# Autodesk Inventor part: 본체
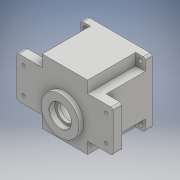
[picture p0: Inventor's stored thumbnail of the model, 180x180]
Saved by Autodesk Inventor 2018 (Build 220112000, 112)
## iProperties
Created: 2020-07
Part Number: 본체
Material: 일반
Document SubType Name: Modeling
Designer: Admin
Density: 1 g/cm^3
Appearance: 기본값
Author: Admin
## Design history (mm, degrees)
sketch "스케치1"
  geometry: L1 (0, -65.8)-(0, 65.8) reference; L2 (-98, 0)-(98, 0) reference; L3 (33, 47)-(-33, 47); L4 (-33, 47)-(-33, 30); L5 (-33, 30)-(-70, 30); L6 (-70, 30)-(-70, -30); L7 (-70, -30)-(-33, -30); L8 (-33, -30)-(-33, -47); L9 (-33, -47)-(33, -47); L10 (33, -47)-(33, -30); L11 (33, -30)-(70, -30); L12 (70, -30)-(70, 30); L13 (70, 30)-(33, 30); L14 (33, 47)-(33, 30); 1 further point
  constraints: 24 end point, 8 perpendicular, 7 point on line, 1 horizontal, 3 other
  dimensions: "d0" = 140 distance between parallel lines of L6 L12; "d1" = 60 distance between parallel lines of L7 L5; "d2" = 66 distance of L3.start L3.end; "d3" = 17 distance of L3.end L4.end; "d4" = 17 distance of L7.end L8.end
extrude "돌출1" new body sketch "스케치1" distance "d5" = 13; taper "d6" = 0 deg
sketch "스케치2"
  geometry: L1 (-33, -47)-(33, -47) reference; L2 (33, -47)-(33, -30) reference; L3 (33, -30)-(70, -30) reference; L4 (70, -30)-(70, 30) reference; L5 (70, 30)-(33, 30) reference; L6 (33, 30)-(33, 47) reference; L7 (33, 47)-(-33, 47) reference; L8 (-33, 47)-(-33, 30) reference; L9 (-33, 30)-(-70, 30) reference; L10 (-70, 30)-(-70, -30) reference; L11 (-70, -30)-(-33, -30) reference; L12 (-33, -30)-(-33, -47) reference; L13 (-47, -47)-(47, -47); L14 (47, -47)-(47, 47); L15 (47, 47)-(-47, 47); L16 (-47, 47)-(-47, -47); L17 (-47, -47)-(47, 47); L18 (47, -47)-(-47, 47); 1 further point
  constraints: 12 end point, 2 midpoint, 2 parallel, 1 horizontal, 1 perpendicular
  dimensions: "d7" = 94 distance of L14.end L15.end; "d8" = 94 distance of L13.end L14.end
extrude "돌출2" join sketch "스케치2" distance "d9" = 67; taper "d10" = 0 deg
sketch "스케치3"
  geometry: L1 (-33, 47)-(33, 47) reference; L2 (-33, 30)-(-33, 47) reference; L3 (-70, 30)-(-33, 30) reference; L4 (-70, -30)-(-70, 30) reference; L5 (-33, -30)-(-70, -30) reference; L6 (-33, -47)-(-33, -30) reference; L7 (33, -47)-(-33, -47) reference; L8 (33, -30)-(33, -47) reference; L9 (70, -30)-(33, -30) reference; L10 (70, 30)-(70, -30) reference; L11 (33, 30)-(70, 30) reference; L12 (33, 47)-(33, 30) reference; L13 (33, 47)-(47, 47) reference; L14 (47, 47)-(47, 30) reference; L15 (47, -30)-(47, -47) reference; L16 (47, -47)-(33, -47) reference; L17 (-33, -47)-(-47, -47) reference; L18 (-47, -47)-(-47, -30) reference; L19 (-47, 30)-(-47, 47) reference; L20 (-47, 47)-(-33, 47) reference; L21 (47, -47)-(-47, -47) reference; L22 (-47, -47)-(-33, -47); L23 (-33, -47)-(-33, -30); L24 (-33, -30)-(-47, -30); L25 (-47, -30)-(-47, -47); L26 (-47, 30)-(-33, 30) reference; L27 (-47, 30)-(-33, 30); L28 (-33, 30)-(-33, 47); L29 (-33, 47)-(-47, 47); L30 (-47, 47)-(-47, 30); L31 (33, 47)-(33, 30) reference; L32 (33, 30)-(47, 30); L33 (47, 30)-(47, 47); L34 (47, 47)-(33, 47); L35 (33, 47)-(33, 30); L36 (33, -47)-(-33, -47) reference; L37 (33, -47)-(47, -47); L38 (47, -47)-(47, -30); L39 (47, -30)-(33, -30); L40 (33, -30)-(33, -47); 1 further point
  constraints: 32 end point, 8 parallel, 4 horizontal, 4 perpendicular
extrude "돌출3" cut sketch "스케치3" distance "d11" = 70; taper "d12" = 0 deg
sketch "스케치8"
  geometry: L1 (98, 0)-(-98, 0) reference; L2 (0, 65.8)-(0, -65.8) reference; C1 r 43 at (0, 0); 1 further point
  constraints: 1 centre point, 1 coincident
  dimensions: "d28" = 86 diameter of C1
extrude "돌출8" cut sketch "스케치8" distance "d29" = 9; taper "d30" = 0 deg
sketch "스케치9"
  geometry: C1 r 43 at (0, 0) reference; C2 r 40 at (0, 0); 1 further point
  constraints: 1 centre point, 1 coincident
  dimensions: "d31" = 80 diameter of C2
extrude "돌출9" cut sketch "스케치9" distance "d32" = 55; taper "d33" = 0 deg
sketch "스케치13"
  geometry: L1 (0, 65.8)-(0, -65.8) reference; L2 (98, 0)-(-98, 0) reference; L3 (-35.778, 3.994)-(-39.8, 3.994); L4 (-35.778, -3.994)-(-39.8, -3.994); C1 r 40 at (0, 0) reference; C2 r 43 at (0, 0) reference; A1 r 40 centre (0, 0) between (-39.8, 3.994) and (-39.8, -3.994) reference; A2 r 36 centre (0, 0) between (-36, 0) and (-35.778, 3.994); A3 r 4 centre (-36, 0) between (-36.222, -3.994) and (-36.222, 3.994); A4 r 40 centre (0, 0) between (-39.8, 3.994) and (-39.8, -3.994); 1 further point
  constraints: 11 point on circle, 4 end point, 3 centre point, 3 point on line, 2 coincident, 2 horizontal
  dimensions: "d45" = 72 diameter of A2; "d46" = 8 diameter of A3
extrude "돌출13" join sketch "스케치13" stored distance "d47" = 7; taper "d48" = 0 deg
sketch "스케치14"
  geometry: L1 (0, 65.8)-(0, -65.8) reference; L2 (98, 0)-(-98, 0) reference; L3 (-35.778, 3.994)-(-39.8, 3.994) reference; L4 (-39.8, -3.994)-(-35.778, -3.994) reference; C1 r 43 at (0, 0) reference; A1 r 40 centre (0, 0) between (-39.8, -3.994) and (-39.8, 3.994) reference; A2 r 4 centre (-36, 0) between (-35.778, -3.994) and (-35.778, 3.994) reference; 2 further points
  constraints: 1 coincident
hole "구멍1" sketch "스케치14" at (-36, 0) diameter "d49" = 3.242; stored, may be unused: countersink angle "d53" = 90 deg, drill point angle "d55" = 118 deg; dims "d50" = 7, "d51" = 4, "d52" = 2, "d54" = 9
sketch "스케치24"
  geometry: L1 (0, 65.8)-(0, -65.8) reference; L2 (98, 0)-(-98, 0) reference; L3 (70, -30)-(70, 30) reference; C1 r 5 at (60, -19); C2 r 5 at (60, 19); C3 r 5 at (-60, -19); C4 r 5 at (-60, 19); 5 further points
  constraints: 4 centre point, 4 symmetric about line, 2 coincident, 2 other
  dimensions: "d67" = 38 distance of point (60, -19) point (60, 19); "d68" = 10 distance from line of L3 point (60, -19); "d69" = 10 distance from line of L3 point (60, 19); "d70" = 19 distance from line of L2 point (60, -19); "d71" = 10 diameter of C1; "d72" = 10 diameter of C2
extrude "돌출17" cut sketch "스케치24" distance "d73" = 5; taper "d74" = 0 deg
sketch "스케치25"
  geometry: L1 (60, 84.8)-(60, -46.8) reference; C1 r 5 at (120, 0) reference; C2 r 5 at (120, 38) reference; C3 r 5 at (0, 38) reference; C4 r 5 at (0, 0) reference; C5 r 2.25 at (120, 0); C6 r 2.25 at (120, 38); C7 r 2.25 at (0, 0); C8 r 2.25 at (0, 38); 1 further point
  constraints: 4 centre point, 2 coincident, 2 symmetric about line, 2 other
  dimensions: "d75" = 4.5 diameter of C5; "d76" = 4.5 diameter of C6
extrude "돌출18" cut sketch "스케치25" extent not by distance; stored distance "d77" = 0; taper "d78" = 0 deg
sketch "스케치26"
  geometry: L1 (-98, 0)-(98, 0) reference; L2 (0, 65.8)-(0, -65.8) reference; L3 (-47, 47)-(47, 47) reference; L4 (47, 47)-(47, -47) reference; L5 (47, -47)-(-47, -47) reference; L6 (-47, -47)-(-47, 47) reference; L7 (40, -40)-(-40, -40); L8 (-40, -40)-(-40, 40); L9 (-40, 40)-(40, 40); L10 (40, 40)-(40, -40); L11 (40, -40)-(-40, 40); L12 (-40, -40)-(40, 40); C1 r 43 at (0, 0) reference; C2 r 3.5 at (40, -40); C3 r 3.5 at (40, 40); C4 r 3.5 at (-40, -40); C5 r 3.5 at (-40, 40); 1 further point
  constraints: 12 end point, 4 centre point, 3 symmetric about line, 2 midpoint, 2 parallel, 1 coincident, 1 horizontal, 1 perpendicular, 3 other
  dimensions: "d79" = 80 distance of L7.end L8.end; "d80" = 80 distance of L8.end L9.end; "d81" = 7 diameter of C2
extrude "돌출19" cut sketch "스케치26" extent not by distance; stored distance "d82" = 5; taper "d83" = 0 deg
sketch "스케치27"
  geometry: L1 (-14, 80)-(80, 80) reference; 2 further points
  constraints: 1 other
  dimensions: "d84" = 40 distance from line of L1 point (32.773, 40)
feature "엠보싱1" sketch "스케치27" dims "d0" = 140, "d1" = 60, "d2" = 66, "d3" = 17, "d4" = 17, "d85" = 0.5, "d86" = 0
fillet "모깎기1" dims "d87" = 3
chamfer "모따기1" distance "d89" = 1; stored, may be unused: second distance "d90" = 2, angle "d91" = 45 deg
sketch "스케치28"
  geometry: L1 (35.778, 3.994)-(39.8, 3.994) reference; L2 (-39.8, 3.994)-(-35.778, 3.994) reference; L3 (-35.778, -3.994)-(-39.8, -3.994) reference; L4 (39.8, -3.994)-(35.778, -3.994) reference; L5 (0, 65.8)-(0, -65.8) reference; L6 (98, 0)-(-98, 0) reference; C1 r 11 at (0, -20); A1 r 40 centre (0, 0) between (39.8, 3.994) and (-39.8, 3.994) reference; A2 r 4 centre (-36, 0) between (-35.778, -3.994) and (-35.778, 3.994) reference; A3 r 40 centre (0, 0) between (-39.8, -3.994) and (39.8, -3.994) reference; A4 r 4 centre (36, 0) between (35.778, 3.994) and (35.778, -3.994) reference; 1 further point
  constraints: 1 centre point, 1 point on line
  dimensions: "d98" = 22 diameter of C1; "d99" = 20 distance from line of C1.centre L6
extrude "돌출20" cut sketch "스케치28" distance "d100" = 7; taper "d101" = 0 deg
sketch "스케치29"
  geometry: L1 (0, 65.8)-(0, -65.8) reference; L2 (-98, 0)-(98, 0) reference; C1 r 27.5 at (0, -11); 1 further point
  constraints: 1 centre point, 1 point on line
  dimensions: "d104" = 55 diameter of C1; "d105" = 11 distance from line of L2 C1.centre
extrude "돌출21" join sketch "스케치29" distance "d106" = 7; taper "d107" = 0 deg
sketch "스케치30"
  geometry: C1 r 11 at (0, 0) reference; C2 r 9.5 at (0, 0); 1 further point
  constraints: 1 centre point, 1 coincident
  dimensions: "d108" = 19 diameter of C2
extrude "돌출22" cut sketch "스케치30" distance "d109" = 3; taper "d110" = 0 deg
sketch "스케치32"
  geometry: C1 r 27.5 at (0, 0) reference; C2 r 16 at (0, 0); 1 further point
  constraints: 1 centre point, 1 coincident
  dimensions: "d111" = 32 diameter of C2
extrude "돌출23" cut sketch "스케치32" distance "d112" = 8.3; taper "d113" = 0 deg
sketch "스케치33"
  geometry: C1 r 16 at (0, 0) reference; C2 r 12.5 at (0, 0); 1 further point
  constraints: 1 centre point, 1 coincident
  dimensions: "d114" = 25 diameter of C2
extrude "돌출24" cut sketch "스케치33" distance "d115" = 4.7; taper "d116" = 0 deg
sketch "스케치34"
  geometry: C1 r 12.5 at (0, 0) reference; C2 r 17.5 at (0, 0); 1 further point
  constraints: 1 centre point, 1 coincident
  dimensions: "d117" = 35 diameter of C2
extrude "돌출25" cut sketch "스케치34" distance "d118" = 10; taper "d119" = 0 deg
chamfer "모따기4" distance "d120" = 0.8; stored, may be unused: second distance "d121" = 2, angle "d122" = 30 deg
fillet "모깎기3" dims "d126" = 3
sketch "스케치36"
  geometry: L1 (35.778, 3.994)-(39.8, 3.994) reference; L2 (-39.8, 3.994)-(-35.778, 3.994) reference; L3 (-35.778, -3.994)-(-39.8, -3.994) reference; L4 (39.8, -3.994)-(35.778, -3.994) reference; C1 r 17.5 at (0, 11) reference; C2 r 11 at (0, -20) reference; A1 r 40 centre (0, 0) between (39.8, 3.994) and (-39.8, 3.994) reference; A2 r 4 centre (-36, 0) between (-35.778, -3.994) and (-35.778, 3.994) reference; A3 r 40 centre (0, 0) between (-39.8, -3.994) and (39.8, -3.994) reference; A4 r 4 centre (36, 0) between (35.778, 3.994) and (35.778, -3.994) reference; A5 r 21 centre (0, 11) between (8.978, -7.984) and (-8.978, -7.984); A6 r 15 centre (0, -20) between (-8.978, -7.984) and (8.978, -7.984); 1 further point
  constraints: 4 point on circle, 2 centre point, 2 coincident
  dimensions: "d129" = 42 diameter of A5; "d130" = 30 diameter of A6
extrude "돌출26" join sketch "스케치36" distance "d131" = 7; taper "d132" = 0 deg
chamfer "모따기6" distance "d133" = 1; stored, may be unused: second distance "d134" = 2, angle "d135" = 45 deg
node "솔리드1"
mirror "미러1"
node "투영된 루프1"
node "투영된 루프2"
node "투영된 루프10"
node "투영된 루프11"
node "투영된 루프15"
node "투영된 루프16"
node "투영된 루프17"
node "투영된 루프19"
node "투영된 루프20"
node "투영된 루프21"
node "투영된 루프23"
other parameters: "d127" = 42
